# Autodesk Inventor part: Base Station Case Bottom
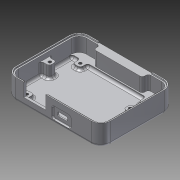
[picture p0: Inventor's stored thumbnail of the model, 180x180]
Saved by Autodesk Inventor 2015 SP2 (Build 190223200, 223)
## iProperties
Created: 2014-11
Part Number: Base Station Case Bottom
Material: PC/ABS-Kunststoff
Document SubType Name: Modeling
Designer: rYan
Mass: 38.3761 g
Surface Area: 210.623 cm^2
Volume: 25.704 cm^3
Density: 1.493 g/cm^3
Appearance: Glatt - weiß
Author: rYan
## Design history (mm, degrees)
sketch "Skizze1"
  geometry: L1 (-37, 28)-(37, 28); L2 (37, 28)-(37, -28); L3 (37, -28)-(-37, -28); L4 (-37, -28)-(-37, 28); L5 (-51.8, 0)-(51.8, 0) reference; L6 (0, 39.2)-(0, -39.2) reference; 1 further point
  constraints: 8 end point, 2 parallel, 1 horizontal, 1 perpendicular, 2 other
  dimensions: "d0" = 74 distance of L2.end L3.end; "d1" = 56 distance of L1.end L2.end
extrude "Extrusion1" new body sketch "Skizze1" distance "d2" = 15; taper "d3" = 0 deg
feature "Wandstärke2" dims "d7" = 2
sketch "Skizze3"
  geometry: L1 (0, 0)-(74, 0) reference; L2 (0, -56)-(0, 0) reference; L3 (74, -56)-(0, -56) reference; L4 (74, 0)-(74, -56) reference; L5 (7, -56)-(13, -56); L6 (13, -56)-(13, -50); L7 (13, -50)-(7, -50); L8 (7, -50)-(7, -56); L9 (61, -56)-(67, -56); L10 (67, -56)-(67, -50); L11 (67, -50)-(61, -50); L12 (61, -50)-(61, -56); L13 (0, 0)-(74, 0); L14 (74, 0)-(74, -6); L15 (0, -6)-(0, 0); L16 (13, -6)-(13, -12); L17 (13, -12)-(7, -12); L18 (7, -12)-(7, -6); L19 (67, -6)-(67, -12); L20 (67, -12)-(61, -12); L21 (61, -12)-(61, -6); L22 (7, -6)-(0, -6); L23 (74, -6)-(67, -6); L24 (61, -6)-(13, -6); L25 (37, 14)-(37, -70) reference; L26 (64, -50)-(64, -56); L27 (10, -50)-(10, -56); L28 (10, -53)-(64, -53); L29 (13, -6)-(7, -6); L30 (10, -12)-(10, -6); L31 (61, -6)-(67, -6); L32 (64, -12)-(64, -6); L33 (64, -9)-(10, -9); 1 further point
  constraints: 56 end point, 12 midpoint, 12 parallel, 4 perpendicular, 3 horizontal, 3 point on line, 2 collinear, 7 other
  dimensions: "d13" = 6 distance of L6.end L7.end; "d15" = 6 distance of L5.end L6.end; "d16" = 6 distance of L16.start L16.end (= d15); "d17" = 44 distance between parallel lines of L28 L33; "d18" = 54 distance of L28.start L28.end; "d19" = 6 distance of L16.end L17.end
extrude "Extrusion2" join sketch "Skizze3" distance "d20" = 2.5; taper "d21" = 0 deg
sketch "Skizze4"
  geometry: L1 (0, -6)-(0, 0) reference; L2 (0, -6)-(7, -6) reference; L3 (7, -6)-(7, -12) reference; L4 (7, -12)-(13, -12) reference; L5 (13, -12)-(13, -6) reference; L6 (13, -6)-(61, -6) reference; L7 (61, -6)-(61, -12) reference; L8 (61, -12)-(67, -12) reference; L9 (67, -12)-(67, -6) reference; L10 (67, -6)-(74, -6) reference; L11 (74, 0)-(74, -6) reference; L12 (0, 0)-(74, 0) reference; L13 (13, -56)-(7, -56) reference; L14 (13, -56)-(13, -50) reference; L15 (13, -50)-(7, -50) reference; L16 (7, -50)-(7, -56) reference; L17 (67, -56)-(61, -56) reference; L18 (67, -56)-(67, -50) reference; L19 (67, -50)-(61, -50) reference; L20 (61, -50)-(61, -56) reference; L21 (67, -9)-(61, -9); L22 (13, -9)-(7, -9); L23 (7, -53)-(13, -53); L24 (61, -53)-(67, -53); 5 further points
  constraints: 12 midpoint, 8 end point
hole "Bohrung1" sketch "Skizze4" at (64, -9), (64, -53), (10, -53), (10, -9) diameter "d22" = 2.459; stored, may be unused: countersink angle "d26" = 90 deg, drill point angle "d28" = 118 deg; dims "d23" = 6, "d24" = 4, "d25" = 2, "d27" = 8
sketch "Skizze5"
  geometry: L1 (0, -56)-(0, -6) reference; L2 (74, -56)-(67, -56) reference; L3 (74, -6)-(74, -56) reference; L4 (0, -25)-(6.5, -25); L5 (6.5, -25)-(6.5, -31); L6 (6.5, -31)-(0, -31); L7 (0, -31)-(0, -25); L8 (74, -25)-(67.5, -25); L9 (67.5, -25)-(67.5, -31); L10 (67.5, -31)-(74, -31); L11 (74, -31)-(74, -25); L12 (37, 14)-(37, -70) reference; L13 (-17.6, -28)-(91.6, -28) reference; L14 (61, -56)-(61, -50) reference; L15 (61, -50)-(67, -50) reference; L16 (67, -50)-(67, -56) reference; L17 (74, -6)-(67, -6) reference; L18 (67, -6)-(67, -12) reference; L19 (67, -12)-(61, -12) reference; L20 (61, -12)-(61, -6) reference; L21 (61, -6)-(13, -6) reference; L22 (13, -6)-(13, -12) reference; L23 (13, -12)-(7, -12) reference; L24 (7, -12)-(7, -6) reference; L25 (7, -6)-(0, -6) reference; L26 (7, -56)-(0, -56) reference; L27 (7, -56)-(7, -50) reference; L28 (7, -50)-(13, -50) reference; L29 (13, -50)-(13, -56) reference; L30 (61, -56)-(13, -56) reference; 1 further point
  constraints: 16 end point, 4 parallel, 2 horizontal, 2 perpendicular, 2 point on line, 4 other
  dimensions: "d31" = 6.5 distance of L10.end L9.end; "d32" = 6 distance of L9.end L8.end
extrude "Extrusion3" join sketch "Skizze5" distance "d34" = 10; taper "d35" = 0 deg
fillet "Rundung3" dims "d43" = 6, "d44" = 8
sketch "Skizze7"
  geometry: L1 (70, 0)-(8, 0) reference; L2 (8, 17)-(70, 17) reference; L3 (14.6, 17)-(32.6, 17); L4 (32.6, 17)-(32.6, 6); L5 (32.6, 6)-(14.6, 6); L6 (14.6, 6)-(14.6, 17); L7 (39, 20.4)-(39, -3.4) reference; L8 (8, 0)-(8, 17) reference; L9 (70, 17)-(70, 0) reference; 1 further point
  constraints: 8 end point, 2 parallel, 1 horizontal, 1 perpendicular, 1 point on line
  dimensions: "d45" = 6 distance between parallel lines of L5 L1; "d46" = 18 distance of L4.end L5.end; "d47" = 6.4 distance between parallel lines of L4 L7
extrude "Extrusion4" cut sketch "Skizze7" distance "d48" = 3; taper "d49" = 0 deg
sketch "Skizze8"
  geometry: L1 (70, 0)-(8, 0) reference; L2 (8, 17)-(14.6, 17) reference; L3 (41.4, 9)-(49.6, 9); L4 (49.6, 9)-(49.6, 5.8); L5 (49.6, 5.8)-(41.4, 5.8); L6 (41.4, 5.8)-(41.4, 9); L7 (39, 20.4)-(39, -3.4) reference; L8 (14.6, 6)-(14.6, 17) reference; L9 (32.6, 17)-(32.6, 6) reference; L10 (32.6, 6)-(14.6, 6) reference; L11 (32.6, 17)-(70, 17) reference; L12 (8, 0)-(8, 17) reference; L13 (70, 17)-(70, 0) reference; 1 further point
  constraints: 8 end point, 2 parallel, 1 horizontal, 1 perpendicular
  dimensions: "d50" = 8.2 distance of L4.end L5.end; "d51" = 3.2 distance of L3.end L4.end; "d52" = 5.8 distance between parallel lines of L5 L1; "d53" = 2.4 distance between parallel lines of L7 L6
extrude "Extrusion5" cut sketch "Skizze8" distance "d54" = 3; taper "d55" = 0 deg
sketch "Skizze9"
  geometry: L1 (49.6, 5.8)-(41.4, 5.8) reference; L2 (41.4, 5.8)-(41.4, 9) reference; L3 (41.4, 9)-(49.6, 9) reference; L4 (49.6, 9)-(49.6, 5.8) reference; L5 (37.5, 12.4)-(53.5, 12.4); L6 (53.5, 12.4)-(53.5, 2.4); L7 (53.5, 2.4)-(37.5, 2.4); L8 (37.5, 2.4)-(37.5, 12.4); L9 (45.5, 5.8)-(45.5, 9); L10 (41.4, 7.4)-(49.6, 7.4); 1 further point
  constraints: 12 end point, 4 midpoint, 2 parallel, 1 horizontal, 1 perpendicular, 2 other
  dimensions: "d56" = 16 distance of L5.start L5.end; "d58" = 10 distance of L7.end L5.start
extrude "Extrusion6" cut sketch "Skizze9" distance "d59" = 1; taper "d60" = 0 deg
fillet "Rundung4" dims "d61" = 2
sketch "Skizze10"
  geometry: L1 (70, -17)-(8, -17) reference; L2 (16.5, -17)-(60.5, -17); L3 (60.5, -17)-(60.5, -16); L4 (60.5, -16)-(16.5, -16); L5 (16.5, -16)-(16.5, -17); L6 (39, 3.4)-(39, -20.4) reference; L7 (8, -2)-(70, -2) reference; L8 (8, -17)-(8, -2) reference; L9 (70, -2)-(70, -17) reference; 1 further point
  constraints: 8 end point, 2 parallel, 1 horizontal, 1 perpendicular, 1 point on line
  dimensions: "d62" = 44 distance of L3.end L4.end; "d64" = 1 distance of L4.end L2.start; "d67" = 22.5 distance between parallel lines of L6 L5
extrude "Extrusion7" cut sketch "Skizze10" distance "d65" = 3; taper "d66" = 0 deg
feature "Lippe3" dims "d80" = 1, "d81" = 1.2, "d82" = 0, "d83" = 0, "d84" = 10 deg, "d85" = 0
sketch "Skizze12"
  geometry: L1 (-37, 3)-(-30.5, 3) reference; L2 (-30.5, 3)-(-30.5, -3) reference; L3 (-30.5, -3)-(-37, -3) reference; L4 (-37, 3)-(-37, -3) reference; L5 (37, -3)-(37, 3) reference; L6 (37, -3)-(30.5, -3) reference; L7 (30.5, -3)-(30.5, 3) reference; L8 (30.5, 3)-(37, 3) reference; L9 (-37, 0)-(-30.5, 0); L10 (30.5, 0)-(37, 0); L11 (0, -42)-(0, 42) reference; 3 further points
  constraints: 4 end point, 4 midpoint, 2 point on line, 1 symmetric about line
  dimensions: "d87" = 4 distance from line of point (-33, 0) L4
hole "Bohrung3" sketch "Skizze12" at (33, 0), (-33, 0) diameter "d88" = 2.459; stored, may be unused: countersink angle "d92" = 90 deg, drill point angle "d94" = 118 deg; dims "d89" = 6, "d90" = 4, "d91" = 6, "d93" = 8
sketch "Skizze15"
  geometry: L1 (2, -6)-(5, -6) reference; L2 (7, -8)-(7, -10) reference; L3 (9, -12)-(11, -12) reference; L4 (13, -10)-(13, -8) reference; L5 (15, -6)-(59, -6) reference; L6 (61, -8)-(61, -10) reference; L7 (63, -12)-(65, -12) reference; L8 (67, -10)-(67, -8) reference; L9 (69, -6)-(72, -6) reference; L10 (6, 0)-(68, 0) reference; L11 (17, 0)-(57, 0); L12 (57, 0)-(57, -5); L13 (57, -5)-(17, -5); L14 (17, -5)-(17, 0); L15 (37, 14)-(37, -70) reference; L16 (74, -6)-(74, -8) reference; L17 (0, -8)-(0, -6) reference; C1 r 1.23 at (10, -9) reference; C2 r 1.23 at (64, -9) reference; A1 r 6 centre (6, -6) between (6, 0) and (0, -6) reference; A2 r 6 centre (68, -6) between (74, -6) and (68, 0) reference; A3 r 2 centre (63, -10) between (61, -10) and (63, -12) reference; A4 r 2 centre (65, -10) between (65, -12) and (67, -10) reference; A5 r 2 centre (69, -8) between (69, -6) and (67, -8) reference; A6 r 2 centre (72, -8) between (74, -8) and (72, -6) reference; A7 r 2 centre (2, -8) between (2, -6) and (0, -8) reference; A8 r 2 centre (5, -8) between (7, -8) and (5, -6) reference; A9 r 2 centre (9, -10) between (7, -10) and (9, -12) reference; A10 r 2 centre (11, -10) between (11, -12) and (13, -10) reference; A11 r 2 centre (15, -8) between (15, -6) and (13, -8) reference; A12 r 2 centre (59, -8) between (61, -8) and (59, -6) reference; 1 further point
  constraints: 8 end point, 1 horizontal, 1 parallel, 1 perpendicular, 1 point on line, 1 other
  dimensions: "d100" = 40 distance of L11.start L11.end; "d109" = 5 distance between parallel lines of L11 L13
extrude "Extrusion10" join sketch "Skizze15" distance "d102" = 11.5; taper "d103" = 0 deg
fillet "Rundung6" dims "d104" = 2
fillet "Rundung7" dims "d105" = 1
fillet "Rundung8" dims "d106" = 1
fillet "Rundung9" dims "d107" = 2
fillet "Rundung10" dims "d108" = 1
fillet "Rundung11" dims "d110" = 1
node "Volumenkörper1"
node "Projizierte Kontur2"
node "Projizierte Kontur3"
node "Projizierte Kontur4"
node "Projizierte Kontur5"
node "Projizierte Kontur6"
node "Projizierte Kontur9"
node "Projizierte Kontur10"
node "Projizierte Kontur11"
node "Projizierte Kontur14"
node "Projizierte Kontur15"
node "Projizierte Kontur17"
